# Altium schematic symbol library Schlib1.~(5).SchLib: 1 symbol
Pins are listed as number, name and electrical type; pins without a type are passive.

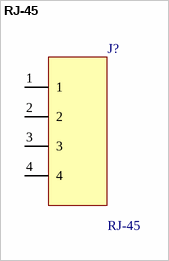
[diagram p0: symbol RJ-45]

## RJ-45
designator J?
pins: 1, 2, 3, 4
